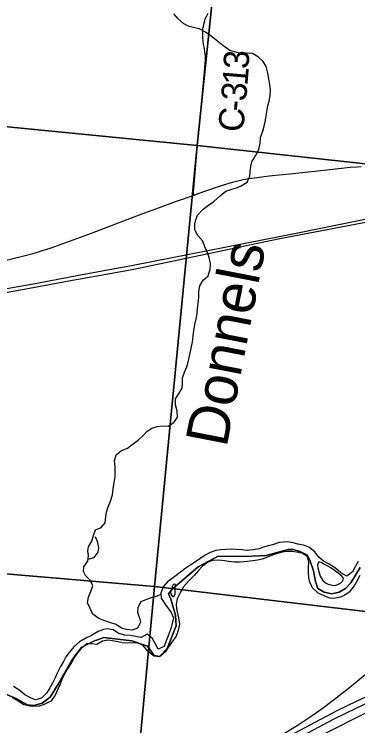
# Model space of a CAD drawing. Extents: x 0 to 1134, y 0 to 440.
# Drawn here: x 839.228 to 840.002, y 360.26 to 361.864 of the extents above; entities that cross this region are included whole.
import ezdxf

# ---------------------------------------------------------------- set-up
doc = ezdxf.new("R2010")
doc.units = 0
for name, color, linetype in [('GM_X_County_Road', 7, 'Continuous'), ('GM_X_County_Road_Text', 7, 'Continuous'), ('GM_X_Interchange_Ramps', 7, 'Continuous'), ('GM_X_Interstate_Route', 7, 'Continuous'), ('GM_X_Major_River', 7, 'Continuous'), ('GM_X_Minor_River', 7, 'Continuous'), ('GM_X_Minor_River_Text', 7, 'Continuous'), ('GM_X_Rail_Line', 7, 'Continuous'), ('GM_X_Section', 7, 'Continuous'), ('GM_X_Township', 7, 'Continuous')]:
    doc.layers.add(name, color=color, linetype=linetype)

msp = doc.modelspace()

# ---------------------------------------------------------------- linework, layer by layer
at = {"layer": 'GM_X_County_Road'}
for points in [[(839.6335, 361.4565), (839.6332, 361.4582), (839.6324, 361.4626), (839.6323, 361.4646), (839.6326, 361.4711), (839.6398, 361.5515), (839.6438, 361.5917), (839.6481, 361.6381), (839.6573, 361.7339), (839.6587, 361.7525), (839.6592, 361.7603), (839.6592, 361.7666), (839.659, 361.7699), (839.6587, 361.7738), (839.6579, 361.7791), (839.6566, 361.7868), (839.655, 361.796), (839.654, 361.8034), (839.6534, 361.8119), (839.653, 361.8194), (839.6531, 361.8264), (839.6535, 361.8306), (839.6544, 361.8361), (839.6555, 361.8416), (839.6568, 361.8471), (839.6588, 361.8532), (839.6612, 361.8588), (839.6655, 361.8664)], [(839.6335, 361.4565), (839.6427, 361.4597), (839.6837, 361.4738), (839.7053, 361.4809), (839.7202, 361.4855), (839.7323, 361.4887), (839.7444, 361.4914), (839.7567, 361.4935), (839.7752, 361.496), (839.803, 361.4994), (839.8556, 361.5051), (839.939, 361.5142), (839.9854, 361.519), (840.0009, 361.5202), (840.0103, 361.5206)], [(839.0072, 361.2627), (839.0171, 361.264), (839.0256, 361.2654), (839.031, 361.2665), (839.0673, 361.2751), (839.122, 361.2885), (839.1618, 361.2981), (839.2079, 361.3092), (839.2501, 361.3196), (839.2758, 361.3264), (839.2917, 361.3311), (839.3115, 361.3377), (839.4021, 361.3707), (839.4671, 361.3953), (839.5139, 361.4132), (839.5554, 361.4284), (839.5935, 361.4426), (839.6335, 361.4565)]]:
    msp.add_lwpolyline(points, dxfattribs=at)
at = {"layer": 'GM_X_Interchange_Ramps'}
msp.add_lwpolyline([(840.2138, 360.572), (840.1882, 360.5444), (840.144, 360.4966), (840.1163, 360.4672), (840.0945, 360.4451), (840.0745, 360.4258), (840.0494, 360.4027), (840.0239, 360.38), (839.9956, 360.3559), (839.974, 360.3382), (839.9471, 360.3172), (839.9223, 360.2986), (839.8995, 360.2825), (839.8841, 360.2721), (839.8657, 360.2605), (839.8259, 360.2365), (839.7536, 360.1942), (839.7234, 360.1773), (839.719, 360.1747), (839.7146, 360.1714), (839.7123, 360.1695), (839.7101, 360.1675), (839.7081, 360.1654), (839.7043, 360.1614)], dxfattribs=at)
at = {"layer": 'GM_X_Interstate_Route'}
for points in [[(839.1866, 359.886), (839.3153, 359.9551), (839.4389, 360.0202), (839.5623, 360.0858), (839.7043, 360.1614), (839.7242, 360.1719), (839.8722, 360.2508), (839.9189, 360.2754), (839.9576, 360.2952), (839.9994, 360.3157), (840.0303, 360.3302), (840.0643, 360.3456), (840.0982, 360.3605), (840.1012, 360.3618), (840.1269, 360.3726), (840.1615, 360.3865), (840.1963, 360.3996), (840.249, 360.4184), (840.3075, 360.4391), (840.372, 360.4617), (840.4251, 360.4808), (840.5015, 360.509), (840.5412, 360.5235), (840.5489, 360.5261)], [(839.8208, 360.2078), (839.8269, 360.211), (839.8818, 360.2403), (839.9478, 360.275), (839.9784, 360.2903), (840.0148, 360.3077), (840.0256, 360.3126)]]:
    msp.add_lwpolyline(points, dxfattribs=at)
at = {"layer": 'GM_X_Major_River'}
for points in [[(840.0031, 360.6307), (839.9975, 360.6198), (839.9907, 360.6071), (839.9776, 360.5975), (839.9644, 360.605), (839.9518, 360.6155), (839.9379, 360.6246), (839.9247, 360.6313), (839.9143, 360.6407), (839.9054, 360.6527), (839.8923, 360.6629), (839.8799, 360.6677), (839.867, 360.6699), (839.8564, 360.6724), (839.8439, 360.6746), (839.8344, 360.674), (839.8249, 360.6731), (839.8103, 360.6685), (839.8004, 360.6657), (839.7897, 360.6629), (839.7801, 360.6593), (839.7663, 360.6569), (839.7515, 360.6557), (839.7416, 360.6571), (839.7294, 360.6574), (839.7165, 360.658), (839.7047, 360.6579), (839.6937, 360.657), (839.6822, 360.6557), (839.67, 360.6511), (839.6588, 360.6448), (839.6487, 360.6378), (839.6364, 360.6297), (839.626, 360.6228), (839.6128, 360.6139), (839.5989, 360.6032), (839.5838, 360.5925), (839.5738, 360.5851), (839.5636, 360.5736), (839.5584, 360.56), (839.5596, 360.5478), (839.5673, 360.5351), (839.5821, 360.5157), (839.5868, 360.5038), (839.585, 360.4936), (839.5817, 360.4819), (839.5764, 360.4668), (839.5708, 360.4521), (839.5663, 360.4393), (839.5529, 360.4331), (839.5448, 360.4473), (839.5393, 360.4577), (839.5278, 360.4671), (839.5139, 360.459), (839.5025, 360.4612)], [(840.0069, 360.5987), (840.0005, 360.5859), (839.9942, 360.5754), (839.9829, 360.5616), (839.9732, 360.5546), (839.9632, 360.5499), (839.9487, 360.5475), (839.9392, 360.5481), (839.9264, 360.553), (839.9132, 360.5593), (839.9002, 360.571), (839.8944, 360.5841), (839.8919, 360.5937), (839.8914, 360.6055), (839.8913, 360.6176), (839.892, 360.6287), (839.8888, 360.6413), (839.8772, 360.6491), (839.8643, 360.6517), (839.8545, 360.6531), (839.8423, 360.6533), (839.832, 360.6517), (839.8213, 360.6489), (839.8113, 360.6453), (839.799, 360.6402), (839.7868, 360.6359), (839.7761, 360.6335), (839.7658, 360.6318), (839.7536, 360.6306), (839.7375, 360.6287), (839.7242, 360.6293), (839.7113, 360.6304), (839.7019, 360.6317), (839.6893, 360.6339), (839.676, 360.6331), (839.6661, 360.6295), (839.6521, 360.6199), (839.6424, 360.6098), (839.6342, 360.6001), (839.6225, 360.5875), (839.6096, 360.5733), (839.6025, 360.5613), (839.595, 360.5466), (839.5932, 360.5345), (839.5941, 360.525), (839.5961, 360.5131), (839.5982, 360.5036), (839.6005, 360.4895)], [(839.9553, 360.6063), (839.9494, 360.611), (839.9419, 360.6165), (839.9332, 360.6209), (839.9257, 360.6249), (839.9201, 360.6284), (839.9167, 360.6292), (839.9136, 360.6289), (839.9116, 360.6225), (839.9126, 360.6164), (839.9143, 360.608), (839.9179, 360.5973), (839.9237, 360.5876), (839.9297, 360.5822), (839.9357, 360.5794), (839.9452, 360.5769), (839.9509, 360.5764), (839.9574, 360.5789), (839.9632, 360.5818), (839.9686, 360.587), (839.9699, 360.5927), (839.9662, 360.5973), (839.9621, 360.6012)], [(839.9621, 360.6012), (839.9553, 360.6063)], [(839.59, 360.5794), (839.5866, 360.5784), (839.5838, 360.5731), (839.5817, 360.5663), (839.5805, 360.561), (839.5819, 360.5564), (839.5841, 360.5526), (839.5875, 360.551), (839.5886, 360.5521), (839.5906, 360.5577), (839.5908, 360.5631), (839.5909, 360.5684), (839.591, 360.5722)], [(839.591, 360.5722), (839.5913, 360.5788), (839.59, 360.5794)], [(839.6005, 360.4895), (839.5979, 360.4747), (839.5931, 360.4626), (839.5836, 360.4491), (839.5762, 360.4379), (839.5702, 360.4274), (839.5559, 360.4159), (839.5426, 360.4173), (839.5296, 360.4287), (839.5177, 360.4418), (839.506, 360.4467), (839.4961, 360.4473), (839.4813, 360.4468), (839.4714, 360.4474), (839.4616, 360.4492), (839.4494, 360.4521), (839.44, 360.4534), (839.427, 360.4514), (839.4143, 360.4434), (839.4018, 360.4452), (839.3919, 360.445), (839.3791, 360.4346), (839.3709, 360.4249), (839.3622, 360.4129), (839.3571, 360.4028), (839.3476, 360.3882), (839.3421, 360.378), (839.3365, 360.366), (839.3312, 360.3528), (839.3268, 360.3426), (839.3208, 360.3291), (839.3106, 360.316), (839.2975, 360.309), (839.2845, 360.3047), (839.2734, 360.3038), (839.2632, 360.3048), (839.2496, 360.3078), (839.235, 360.3172), (839.2241, 360.3232)], [(839.5025, 360.4612), (839.49, 360.4641), (839.4771, 360.4644), (839.4643, 360.4685), (839.4515, 360.4764), (839.4386, 360.4786), (839.4291, 360.4776), (839.4176, 360.473), (839.4026, 360.4638), (839.3895, 360.4576), (839.3752, 360.4495), (839.3624, 360.438), (839.3519, 360.4253), (839.3444, 360.4156), (839.3389, 360.4055), (839.3325, 360.3938), (839.325, 360.3788), (839.3202, 360.3686), (839.3142, 360.3566), (839.3086, 360.3457), (839.3019, 360.3344), (839.2895, 360.3225), (839.2761, 360.319), (839.2663, 360.3223), (839.2523, 360.3298), (839.2412, 360.3399), (839.2269, 360.349)]]:
    msp.add_lwpolyline(points, dxfattribs=at)
at = {"layer": 'GM_X_Minor_River'}
for points in [[(839.6933, 361.4555), (839.7052, 361.4648), (839.7189, 361.47), (839.7288, 361.4729), (839.7395, 361.4773), (839.7533, 361.4855), (839.7588, 361.4987), (839.7597, 361.5086), (839.7614, 361.5215), (839.7638, 361.5313), (839.7719, 361.5449), (839.7793, 361.5592), (839.7821, 361.5732), (839.7834, 361.5861), (839.7882, 361.6001), (839.7913, 361.6118), (839.7937, 361.6217), (839.7958, 361.6338), (839.7971, 361.6444), (839.7999, 361.6573), (839.8023, 361.6683), (839.8047, 361.68), (839.8057, 361.6941), (839.8043, 361.7051), (839.8022, 361.718), (839.7993, 361.7313), (839.7957, 361.7458), (839.7894, 361.7577), (839.7785, 361.7673), (839.7653, 361.7754), (839.752, 361.776), (839.7387, 361.7757), (839.7273, 361.7781), (839.7141, 361.7821), (839.6986, 361.7937), (839.6836, 361.8052), (839.6712, 361.8153), (839.6591, 361.8234), (839.6448, 361.8308), (839.6349, 361.8332), (839.6224, 361.8363), (839.6107, 361.8426), (839.5976, 361.8533), (839.5882, 361.8645)], [(839.5587, 360.5564), (839.5504, 360.5524), (839.5366, 360.5488), (839.526, 360.5448), (839.5137, 360.54), (839.5064, 360.5268), (839.5062, 360.5165), (839.5106, 360.5032), (839.5128, 360.4937), (839.5062, 360.4805), (839.4936, 360.4757), (839.4811, 360.4773), (839.4701, 360.4805), (839.458, 360.4886), (839.444, 360.4933), (839.43, 360.4977), (839.4191, 360.5024), (839.4055, 360.5116), (839.3996, 360.5246), (839.3933, 360.5376), (839.3953, 360.5505), (839.4008, 360.563), (839.4052, 360.5754), (839.3996, 360.5884), (839.3891, 360.5988), (839.3843, 360.6083), (839.3852, 360.6186), (839.3944, 360.631), (839.3954, 360.6439), (839.3943, 360.6541), (839.3956, 360.6636), (839.4034, 360.6764), (839.4066, 360.6893), (839.4113, 360.7018), (839.4239, 360.7069), (839.4331, 360.7178), (839.4348, 360.7319), (839.4361, 360.7417), (839.44, 360.7535), (839.4451, 360.7663), (839.4495, 360.7811), (839.4508, 360.7947), (839.4536, 360.8083), (839.4557, 360.8212), (839.4558, 360.8307), (839.4556, 360.8448), (839.4542, 360.8577), (839.4578, 360.8709), (839.4701, 360.8807), (839.4831, 360.8862), (839.4934, 360.8933), (839.5076, 360.9038), (839.5187, 360.9142), (839.528, 360.924), (839.5383, 360.9307), (839.5501, 360.9351), (839.5631, 360.9361), (839.5752, 360.9352), (839.5882, 360.9438), (839.5964, 360.9562), (839.5954, 360.9691), (839.5914, 360.9836), (839.5919, 360.9973), (839.5997, 361.0097), (839.607, 361.0218), (839.6076, 361.032), (839.6073, 361.0446), (839.612, 361.0574), (839.6171, 361.0695), (839.6203, 361.0805), (839.6227, 361.0903), (839.6251, 361.1036), (839.6276, 361.1149), (839.6296, 361.1252), (839.6313, 361.1388), (839.6334, 361.1555), (839.6362, 361.1676), (839.639, 361.1805), (839.6403, 361.1903), (839.6412, 361.2002), (839.6428, 361.2127), (839.6441, 361.2252), (839.6443, 361.2389), (839.6463, 361.2518), (839.6537, 361.2642), (839.6649, 361.2747), (839.67, 361.2887), (839.6701, 361.302), (839.6676, 361.3153), (839.6632, 361.3282), (839.6577, 361.3397), (839.6533, 361.3523), (839.6421, 361.3653), (839.6354, 361.3783), (839.6355, 361.3908), (839.6372, 361.4003), (839.6415, 361.4113), (839.6542, 361.4244), (839.6661, 361.4338), (839.6783, 361.442), (839.6933, 361.4555)], [(839.3948, 360.6361), (839.4082, 360.6399), (839.4171, 360.6516), (839.4187, 360.6611), (839.4166, 360.6736), (839.4111, 360.6858)]]:
    msp.add_lwpolyline(points, dxfattribs=at)
at = {"layer": 'GM_X_Rail_Line'}
for points in [[(841.7289, 361.7267), (841.636, 361.7122), (841.1421, 361.6188), (840.658, 361.5251), (840.1995, 361.4383), (839.8708, 361.3715), (839.4959, 361.2977), (839.3695, 361.2741), (839.2837, 361.2579), (839.1515, 361.2347), (839.0452, 361.2426), (838.9712, 361.2584), (838.8788, 361.2852), (838.7922, 361.3241), (838.7273, 361.3639), (838.6544, 361.4226), (838.4388, 361.6154), (838.1628, 361.8666)], [(836.2484, 359.8987), (836.4737, 360.0545), (836.8961, 360.3143), (837.1477, 360.5217), (837.2503, 360.5989), (837.3703, 360.682), (837.4559, 360.737), (837.6488, 360.8541), (837.8041, 360.9469), (837.8854, 360.994), (838.2343, 361.1415), (838.6187, 361.2463), (838.9046, 361.2586), (838.9722, 361.246), (839.0457, 361.2318), (839.1496, 361.2259), (839.2509, 361.2446), (839.3511, 361.2632), (839.494, 361.2889), (839.8268, 361.3583), (841.1445, 361.6094), (841.7312, 361.712), (841.7847, 361.7229)], [(837.4519, 358.9594), (838.5805, 359.5329), (839.8845, 360.2211), (840.0594, 360.3089), (840.4072, 360.496), (840.567, 360.6027), (840.7229, 360.7078)]]:
    msp.add_lwpolyline(points, dxfattribs=at)
at = {"layer": 'GM_X_Section'}
for points in [[(838.749, 362.6588), (839.7438, 362.5638), (839.6405, 361.5684), (838.6563, 361.665)], [(839.7438, 362.5638), (840.7489, 362.4766), (840.6525, 361.4576), (839.6405, 361.5684)], [(839.6405, 361.5684), (839.544, 360.574), (838.5547, 360.6582), (838.6563, 361.665)], [(839.6405, 361.5684), (840.6525, 361.4576), (840.5521, 360.4549), (839.544, 360.574)], [(838.5547, 360.6582), (839.544, 360.574), (839.4487, 359.5561), (838.4659, 359.6429)], [(839.544, 360.574), (840.5521, 360.4549), (840.4525, 359.4584), (839.4699, 359.5539), (839.4487, 359.5561)]]:
    msp.add_lwpolyline(points, close=True, dxfattribs=at)
at = {"layer": 'GM_X_Township'}
for points in [[(839.161, 360.351), (839.2311, 360.3225), (839.257, 360.308), (839.2585, 360.3072), (839.2727, 360.3061), (839.2913, 360.3116), (839.3089, 360.3247), (839.3275, 360.3543), (839.3581, 360.408), (839.3757, 360.432), (839.3809, 360.4374), (839.4074, 360.4507), (839.4304, 360.4594), (839.4929, 360.4518), (839.5283, 360.44), (839.5439, 360.4188), (839.5559, 360.4162), (839.5732, 360.4348), (839.5932, 360.4855), (839.5919, 360.5095), (839.5812, 360.5455), (839.5759, 360.5575), (839.5839, 360.5681), (839.6426, 360.6188), (839.6879, 360.6428), (839.7479, 360.6415), (839.7959, 360.6441), (839.8453, 360.6574), (839.8573, 360.6574), (839.872, 360.6534), (839.888, 360.6454), (839.8946, 360.6334), (839.9027, 360.6094), (839.9067, 360.5854), (839.912, 360.5694), (839.9267, 360.5614), (839.944, 360.5574), (839.96, 360.5614), (839.9747, 360.5694), (839.9867, 360.5827), (840.008, 360.6174)], [(840.008, 360.6174), (839.9867, 360.5827), (839.9747, 360.5694), (839.96, 360.5614), (839.944, 360.5574), (839.9267, 360.5614), (839.912, 360.5694), (839.9067, 360.5854), (839.9027, 360.6094), (839.8946, 360.6334), (839.888, 360.6454), (839.872, 360.6534), (839.8573, 360.6574), (839.8453, 360.6574), (839.7959, 360.6441), (839.7479, 360.6415), (839.6879, 360.6428), (839.6426, 360.6188), (839.5839, 360.5681), (839.5759, 360.5575), (839.5812, 360.5455), (839.5919, 360.5095), (839.5932, 360.4855), (839.5732, 360.4348), (839.5559, 360.4162), (839.5439, 360.4188), (839.5283, 360.44), (839.4929, 360.4518), (839.4304, 360.4594), (839.4074, 360.4507), (839.3809, 360.4374), (839.3757, 360.432), (839.3581, 360.408), (839.3275, 360.3543), (839.3089, 360.3247), (839.2913, 360.3116), (839.2727, 360.3061), (839.2585, 360.3072), (839.257, 360.308), (839.2311, 360.3225), (839.161, 360.351)]]:
    msp.add_lwpolyline(points, dxfattribs=at)

# ---------------------------------------------------------------- texts
at = {"layer": 'GM_X_County_Road_Text'}
for s, rotation, p in [('3', 88.2328, (839.7566, 361.7399)), ('1', 85.242, (839.7535, 361.7017)), ('3', 84.9225, (839.7504, 361.6665)), ('-', 84.8298, (839.7482, 361.6432)), ('C', 84.8098, (839.744, 361.5967))]:
    msp.add_text(s, height=0.0568, rotation=rotation, dxfattribs=at).set_placement(p)
at = {"layer": 'GM_X_Minor_River_Text'}
msp.add_text('Donnels', height=0.09466, rotation=78.9998, dxfattribs=at).set_placement((839.7065, 360.8857))

doc.saveas('drawing.dxf')
